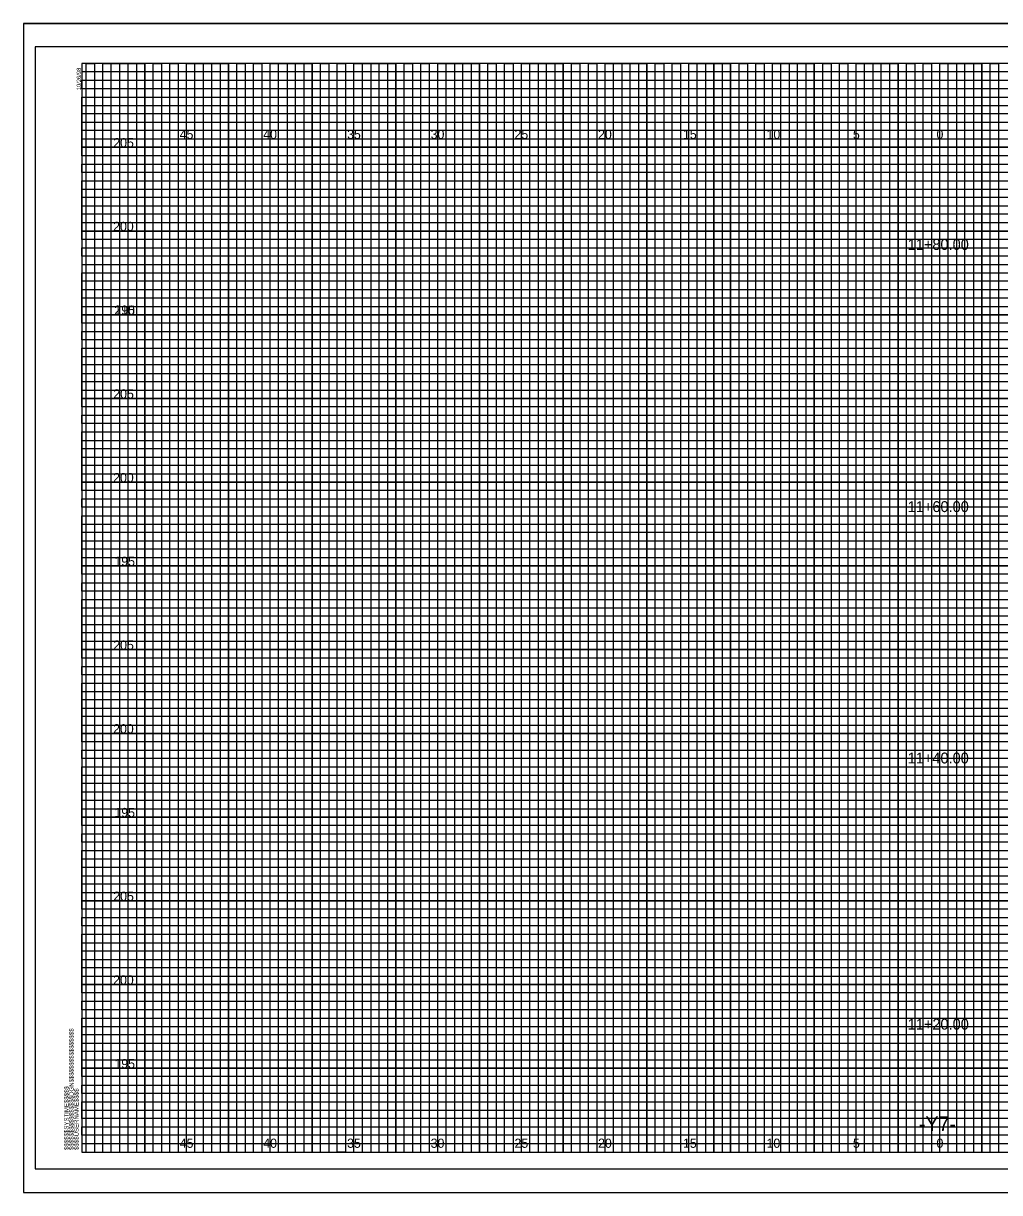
# Model space of a CAD drawing. Extents: x -4 to 103, y -2 to 351.
# Drawn here: x -3.5 to 54.8, y 68.4 to 138.2 of the extents above; entities that cross this region are included whole.
import ezdxf

# ---------------------------------------------------------------- set-up
doc = ezdxf.new("R2010")
doc.units = 0
for name, color, linetype in [('Exist XS Ground Line', 7, 'Continuous'), ('Old_Level_10', 7, 'Continuous'), ('Old_Level_16', 7, 'Continuous'), ('Old_Level_3', 7, 'Continuous'), ('Old_Level_4', 7, 'Continuous'), ('Old_Level_5', 7, 'Continuous'), ('Old_Level_6', 7, 'Continuous'), ('Old_Level_8', 7, 'Continuous'), ('Prop XS Finish Grade', 7, 'Continuous'), ('Prop XS SE Text', 7, 'Continuous'), ('Prop XS Subgrade Earthwork', 7, 'Continuous')]:
    doc.layers.add(name, color=color, linetype=linetype)

msp = doc.modelspace()

# ---------------------------------------------------------------- linework, layer by layer
at = {"layer": 'Old_Level_10'}
for p, q in [((1.25, 70.825), (1.25, 135.825)), ((3.75, 70.825), (3.75, 135.825)), ((6.25, 70.825), (6.25, 135.825)), ((8.75, 70.825), (8.75, 135.825)), ((11.25, 70.825), (11.25, 135.825)), ((13.75, 70.825), (13.75, 135.825)), ((16.25, 70.825), (16.25, 135.825)), ((18.75, 70.825), (18.75, 135.825)), ((21.25, 70.825), (21.25, 135.825)), ((23.75, 70.825), (23.75, 135.825)), ((26.25, 70.825), (26.25, 135.825)), ((28.75, 70.825), (28.75, 135.825)), ((31.25, 70.825), (31.25, 135.825)), ((33.75, 70.825), (33.75, 135.825)), ((36.25, 70.825), (36.25, 135.825)), ((38.75, 70.825), (38.75, 135.825)), ((41.25, 70.825), (41.25, 135.825)), ((43.75, 70.825), (43.75, 135.825)), ((46.25, 70.825), (46.25, 135.825)), ((48.75, 70.825), (48.75, 135.825)), ((51.25, 70.825), (51.25, 135.825)), ((53.75, 70.825), (53.75, 135.825)), ((0, 133.325), (74.25, 133.325)), ((0, 130.825), (102.5, 130.825)), ((0, 128.325), (102.5, 128.325)), ((0, 125.825), (102.5, 125.825)), ((0, 123.325), (102.5, 123.325)), ((0, 120.825), (102.5, 120.825)), ((0, 118.325), (102.5, 118.325)), ((0, 115.825), (102.5, 115.825)), ((0, 113.325), (102.5, 113.325)), ((0, 110.825), (102.5, 110.825)), ((0, 108.325), (102.5, 108.325)), ((0, 105.825), (102.5, 105.825)), ((0, 103.325), (102.5, 103.325)), ((0, 100.825), (102.5, 100.825)), ((0, 98.325), (102.5, 98.325)), ((0, 95.825), (102.5, 95.825)), ((0, 93.325), (102.5, 93.325)), ((0, 90.825), (102.5, 90.825)), ((0, 88.325), (102.5, 88.325)), ((0, 85.825), (102.5, 85.825)), ((0, 83.325), (102.5, 83.325)), ((0, 80.825), (102.5, 80.825)), ((0, 78.325), (102.5, 78.325)), ((0, 75.825), (102.5, 75.825)), ((0, 73.325), (102.5, 73.325))]:
    msp.add_line(p, q, dxfattribs=at)
at = {"layer": 'Old_Level_3'}
for p, q in [((-3.5, 138.225), (103.4, 138.225)), ((-3.5, 138.225), (-3.5, 68.4)), ((-3.5, 68.4), (102.1625, 68.4))]:
    msp.add_line(p, q, dxfattribs=at)
at = {"layer": 'Old_Level_4'}
for points in [[(0.25, 70.825), (0.25, 135.825), (0.75, 135.825), (0.75, 70.825), (1.75, 70.825), (1.75, 135.825), (2.25, 135.825), (2.25, 70.825), (2.75, 70.825), (2.75, 135.825), (3.25, 135.825), (3.25, 70.825), (4.25, 70.825), (4.25, 135.825), (4.75, 135.825), (4.75, 70.825), (5.25, 70.825), (5.25, 135.825), (5.75, 135.825), (5.75, 70.825), (6.75, 70.825), (6.75, 135.825), (7.25, 135.825), (7.25, 70.825), (7.75, 70.825), (7.75, 135.825), (8.25, 135.825), (8.25, 70.825), (9.25, 70.825), (9.25, 135.825), (9.75, 135.825), (9.75, 70.825), (10.25, 70.825), (10.25, 135.825), (10.75, 135.825), (10.75, 70.825), (11.75, 70.825), (11.75, 135.825), (12.25, 135.825), (12.25, 70.825), (12.75, 70.825), (12.75, 135.825), (13.25, 135.825), (13.25, 70.825), (14.25, 70.825), (14.25, 135.825), (14.75, 135.825), (14.75, 70.825), (15.75, 70.825), (15.25, 70.825), (15.25, 135.825), (15.75, 135.825), (15.75, 70.825), (16.75, 70.825), (16.75, 135.825), (17.25, 135.825), (17.25, 70.825), (17.75, 70.825), (17.75, 135.825), (18.25, 135.825), (18.25, 70.825), (19.25, 70.825), (19.25, 135.825), (19.75, 135.825), (19.75, 70.825), (20.25, 70.825), (20.25, 135.825), (20.75, 135.825), (20.75, 70.825), (21.75, 70.825), (21.75, 135.825), (22.25, 135.825), (22.25, 70.825), (22.75, 70.825), (22.75, 135.825), (23.25, 135.825), (23.25, 70.825), (24.25, 70.825), (24.25, 135.825), (24.75, 135.825), (24.75, 70.825), (25.25, 70.825), (25.25, 135.825), (25.75, 135.825), (25.75, 70.825), (26.75, 70.825), (26.75, 135.825), (27.25, 135.825), (27.25, 70.825), (27.75, 70.825), (27.75, 135.825), (28.25, 135.825), (28.25, 70.825), (29.25, 70.825), (29.25, 135.825), (29.75, 135.825), (29.75, 70.825), (30.25, 70.825), (30.25, 135.825), (30.75, 135.825), (30.75, 70.825)], [(30.75, 70.825), (31.75, 70.825), (31.75, 135.825), (32.25, 135.825), (32.25, 70.825), (32.75, 70.825), (32.75, 135.825), (33.25, 135.825), (33.25, 70.825), (34.25, 70.825), (34.25, 135.825), (34.75, 135.825), (34.75, 70.825), (35.25, 70.825), (35.25, 135.825), (35.75, 135.825), (35.75, 70.825), (36.75, 70.825), (36.75, 135.825), (37.25, 135.825), (37.25, 70.825), (37.75, 70.825), (37.75, 135.825), (37.75, 70.825)], [(38.25, 135.825), (38.25, 70.825), (39.25, 70.825), (39.25, 135.825), (39.75, 135.825), (39.75, 70.825), (40.25, 70.825), (40.25, 135.825), (40.75, 135.825), (40.75, 70.825), (41.75, 70.825), (41.75, 135.825), (42.25, 135.825), (42.25, 70.825), (42.75, 70.825), (42.75, 135.825), (43.25, 135.825), (43.25, 70.825), (43.75, 70.825), (44.25, 70.825), (44.25, 135.825), (44.75, 135.825), (44.75, 70.825), (45.25, 70.825), (45.25, 135.825), (45.75, 135.825), (45.75, 70.825), (46.75, 70.825), (46.75, 135.825), (47.25, 135.825), (47.25, 70.825), (47.75, 70.825), (47.75, 135.825), (48.25, 135.825), (48.25, 70.825), (49.25, 70.825), (49.25, 135.825), (49.75, 135.825), (49.75, 70.825), (50.25, 70.825), (50.25, 135.825), (50.75, 135.825), (50.75, 70.825), (51.75, 70.825), (51.75, 135.825), (52.25, 135.825), (52.25, 70.825), (52.75, 70.825), (52.75, 135.825), (53.25, 135.825), (53.25, 70.825), (54.25, 70.825), (54.25, 135.825), (54.75, 135.825), (54.75, 70.825), (55.25, 70.825)], [(0, 132.825), (0, 133.825), (74.25, 133.825), (74.25, 134.325), (0, 134.325), (0, 134.825), (74.25, 134.825), (74.25, 135.325), (0, 135.325)], [(102.5, 132.825), (0, 132.825)], [(102.5, 131.825), (0, 131.825), (0, 132.325), (102.5, 132.325)], [(102.5, 130.325), (0, 130.325), (0, 131.325), (102.5, 131.325)], [(102.5, 129.325), (0, 129.325), (0, 129.825), (102.5, 129.825)], [(102.5, 127.825), (0, 127.825), (0, 128.825), (102.5, 128.825)], [(102.5, 126.825), (0, 126.825), (0, 127.325), (102.5, 127.325)], [(102.5, 125.325), (0, 125.325), (0, 126.325), (102.5, 126.325)], [(102.5, 124.325), (0, 124.325), (0, 124.825), (102.5, 124.825)], [(0, 123.825), (102.5, 123.825)], [(102.5, 122.825), (0, 122.825)], [(102.5, 121.825), (0, 121.825), (0, 122.325), (102.5, 122.325)], [(102.5, 120.325), (0, 120.325), (0, 121.325), (102.5, 121.325)], [(102.5, 119.325), (0, 119.325), (0, 119.825), (102.5, 119.825)], [(102.5, 117.825), (0, 117.825), (0, 118.825), (102.5, 118.825)], [(102.5, 116.825), (0, 116.825), (0, 117.325), (102.5, 117.325)], [(102.5, 115.325), (0, 115.325), (0, 116.325), (102.5, 116.325)], [(102.5, 114.325), (0, 114.325), (0, 114.825), (102.5, 114.825)], [(102.5, 112.825), (0, 112.825), (0, 113.825), (102.5, 113.825)], [(102.5, 111.825), (0, 111.825), (0, 112.325), (102.5, 112.325)], [(102.5, 110.325), (0, 110.325), (0, 111.325), (102.5, 111.325)], [(102.5, 109.325), (0, 109.325), (0, 109.825), (102.5, 109.825)], [(102.5, 107.825), (0, 107.825), (0, 108.825), (102.5, 108.825)], [(102.5, 106.825), (0, 106.825), (0, 107.325), (102.5, 107.325)], [(102.5, 105.325), (0, 105.325), (0, 106.325), (102.5, 106.325)], [(102.5, 104.325), (0, 104.325), (0, 104.825), (102.5, 104.825)], [(102.5, 102.825), (0, 102.825), (0, 103.825), (102.5, 103.825)], [(102.5, 101.825), (0, 101.825), (0, 102.325)], [(0, 102.325), (102.5, 102.325)], [(102.5, 100.325), (0, 100.325), (0, 101.325), (102.5, 101.325)], [(102.5, 99.325), (0, 99.325), (0, 99.825), (102.5, 99.825)], [(102.5, 97.825), (0, 97.825), (0, 98.825), (102.5, 98.825)], [(102.5, 96.825), (0, 96.825), (0, 97.325), (102.5, 97.325)], [(102.5, 95.325), (0, 95.325), (0, 96.325), (102.5, 96.325)], [(102.5, 94.325), (0, 94.325), (0, 94.825), (102.5, 94.825)], [(102.5, 92.825), (0, 92.825), (0, 93.825), (102.5, 93.825)], [(102.5, 91.825), (0, 91.825), (0, 92.325), (102.5, 92.325)], [(102.5, 90.325), (0, 90.325), (0, 91.325), (102.5, 91.325)], [(102.5, 89.325), (0, 89.325), (0, 89.825), (102.5, 89.825)], [(102.5, 87.825), (0, 87.825), (0, 88.825), (102.5, 88.825)], [(102.5, 86.825), (0, 86.825), (0, 87.325), (102.5, 87.325)], [(102.5, 85.325), (0, 85.325), (0, 86.325), (102.5, 86.325)], [(102.5, 84.325), (0, 84.325), (0, 84.825), (102.5, 84.825)], [(102.5, 82.825), (0, 82.825), (0, 83.825), (102.5, 83.825)], [(102.5, 81.825), (0, 81.825), (0, 82.325), (102.5, 82.325)], [(102.5, 80.325), (0, 80.325), (0, 81.325), (102.5, 81.325)], [(102.5, 79.325), (0, 79.325), (0, 79.825), (102.5, 79.825)], [(102.5, 77.825), (0, 77.825), (0, 78.825), (102.5, 78.825)], [(102.5, 76.825), (0, 76.825), (0, 77.325), (102.5, 77.325)], [(102.5, 75.325), (0, 75.325), (0, 76.325), (102.5, 76.325)], [(102.5, 74.325), (0, 74.325), (0, 74.825), (102.5, 74.825)], [(102.5, 72.825), (0, 72.825), (0, 73.825), (102.5, 73.825)], [(102.5, 71.825), (0, 71.825), (0, 72.325), (102.5, 72.325)], [(0, 71.325), (102.5, 71.325)]]:
    msp.add_lwpolyline(points, dxfattribs=at)
at = {"layer": 'Old_Level_5'}
msp.add_lwpolyline([(103.4, 138.225), (-3.5, 138.225), (-3.5, 68.4), (103.4, 68.4)], close=True, dxfattribs=at)
at = {"layer": 'Old_Level_6'}
for p, q in [((0, 70.825), (0, 70.825)), ((0, 70.825), (0, 70.825)), ((-3.5, 68.4), (103.4, 68.4))]:
    msp.add_line(p, q, dxfattribs=at)
msp.add_lwpolyline([(102.5, 135.825), (0, 135.825), (0, 70.825), (102.5, 70.825)], close=True, dxfattribs=at)
at = {"layer": 'Old_Level_8'}
for points in [[(1.25, 70.825), (1.25, 135.825), (3.75, 135.825), (3.75, 70.825), (6.25, 70.825), (6.25, 135.825), (8.75, 135.825), (8.75, 70.825), (11.25, 70.825), (11.25, 135.825), (13.75, 135.825), (13.75, 70.825), (16.25, 70.825), (16.25, 135.825), (18.75, 135.825), (18.75, 70.825), (21.25, 70.825), (21.25, 135.825), (23.75, 135.825), (23.75, 70.825), (26.25, 70.825), (26.25, 135.825), (28.75, 135.825), (28.75, 70.825), (31.25, 70.825), (31.25, 135.825), (33.75, 135.825), (33.75, 70.825), (36.25, 70.825), (36.25, 135.825), (38.75, 135.825), (38.75, 70.825), (41.25, 70.825), (41.25, 135.825), (43.75, 135.825), (43.75, 70.825), (46.25, 70.825), (46.25, 135.825), (48.75, 135.825), (48.75, 70.825), (51.25, 70.825), (51.25, 135.825), (53.75, 135.825), (53.75, 70.825)], [(102.5, 130.825), (0, 130.825), (0, 133.325), (74.25, 133.325)], [(102.5, 125.825), (0, 125.825), (0, 128.325), (102.5, 128.325)], [(102.5, 120.825), (0, 120.825), (0, 123.325), (102.5, 123.325)], [(102.5, 115.825), (0, 115.825), (0, 118.325), (102.5, 118.325)], [(102.5, 110.825), (0, 110.825), (0, 113.325), (102.5, 113.325)], [(102.5, 105.825), (0, 105.825), (0, 108.325), (102.5, 108.325)], [(102.5, 100.825), (0, 100.825), (0, 103.325), (102.5, 103.325)], [(102.5, 95.825), (0, 95.825), (0, 98.325), (102.5, 98.325)], [(102.5, 90.825), (0, 90.825), (0, 93.325), (102.5, 93.325)], [(102.5, 85.825), (0, 85.825), (0, 88.325), (102.5, 88.325)], [(102.5, 80.825), (0, 80.825), (0, 83.325), (102.5, 83.325)], [(102.5, 75.825), (0, 75.825), (0, 78.325), (102.5, 78.325)], [(0, 73.325), (102.5, 73.325)]]:
    msp.add_lwpolyline(points, dxfattribs=at)
at = {"layer": 'Prop XS SE Text'}
msp.add_lwpolyline([(103, 136.825), (-2.8, 136.825), (-2.8, 69.825), (103, 69.825)], close=True, dxfattribs=at)

# ---------------------------------------------------------------- texts
at = {"layer": 'Exist XS Ground Line'}
msp.add_text('-Y7-', height=0.875, dxfattribs=at).set_placement((49.9985, 72.075))
at = {"layer": 'Old_Level_16'}
for s, p in [('45', (5.8399, 131.325)), ('40', (10.8313, 131.325)), ('35', (15.8399, 131.325)), ('30', (20.8313, 131.325)), ('25', (25.8399, 131.325)), ('20', (30.8313, 131.325)), ('15', (35.9058, 131.325)), ('10', (40.8971, 131.325)), ('5', (46.0574, 131.325)), ('0', (51.0488, 131.325)), ('0', (51.0488, 131.325)), ('45', (5.8399, 71.075)), ('40', (10.8313, 71.075)), ('35', (15.8399, 71.075)), ('30', (20.8313, 71.075)), ('25', (25.8399, 71.075)), ('20', (30.8313, 71.075)), ('15', (35.9058, 71.075)), ('10', (40.8971, 71.075)), ('5', (46.0574, 71.075)), ('0', (51.0488, 71.075)), ('0', (51.0488, 71.075))]:
    msp.add_text(s, height=0.55, dxfattribs=at).set_placement(p)
at = {"layer": 'Old_Level_6'}
for s, height, p in [('10/26/98', 0.25, (-0.0625, 134.2345)), ('$$$$$$$$$$$$$$$$DGN$$$$$$$$$$$$$$$$', 0.2625, (-0.5, 70.95)), ('$$$$$$SYSTIME$$$$$', 0.2625, (-0.7973, 70.9497)), ('$$$$USERNAME$$$$', 0.2625, (-0.2, 70.95))]:
    msp.add_text(s, height=height, rotation=90, dxfattribs=at).set_placement(p)
at = {"layer": 'Old_Level_8'}
msp.add_text('040397', height=0.0025, rotation=90, dxfattribs=at).set_placement((-0.0007, 135.8114))
at = {"layer": 'Prop XS Finish Grade'}
for s, p in [('205', (1.8724, 130.825)), ('200', (1.8638, 125.825)), ('210', (1.9296, 120.825)), ('195', (1.9383, 120.825)), ('205', (1.8724, 115.825)), ('200', (1.8638, 110.825)), ('195', (1.9383, 105.825)), ('205', (1.8724, 100.825)), ('200', (1.8638, 95.825)), ('195', (1.9383, 90.825)), ('205', (1.8724, 85.825)), ('200', (1.8638, 80.825)), ('195', (1.9383, 75.825))]:
    msp.add_text(s, height=0.55, dxfattribs=at).set_placement(p)
at = {"layer": 'Prop XS Subgrade Earthwork'}
for s, p in [('11+80.00', (49.3286, 124.6982)), ('11+60.00', (49.3286, 109.0424)), ('11+40.00', (49.3286, 94.0291)), ('11+20.00', (49.3286, 78.1336))]:
    msp.add_text(s, height=0.65, dxfattribs=at).set_placement(p)

doc.saveas('drawing.dxf')
